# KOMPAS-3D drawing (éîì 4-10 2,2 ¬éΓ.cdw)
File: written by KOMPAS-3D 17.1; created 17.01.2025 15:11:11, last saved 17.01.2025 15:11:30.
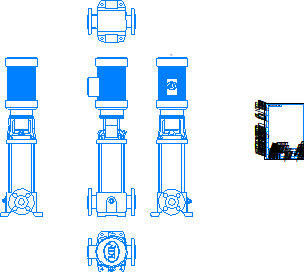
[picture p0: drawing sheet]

Sheet 1: A4, portrait

Title block, sheet 1: name: ВМН 4-10 2,2 кВт; designation: ВМН 4-10 2,2 кВт; sheets: 1; sheet format: A4; stored path: \\adlc.lan\data\АДЛ_ПКД\3D-модели\ADL production\Насосы ГРАНПАМП\Насосы ВМН\ВМН4\KOMPAS 2D\ВМН 4-10 2,2 кВт.cdw

Views: Вид 1, Спереди, Проекционный вид 2, Проекционный вид 3, Проекционный вид 4, Проекционный вид 5
Referenced files in \\adlc.lan\data\АДЛ_ПКД\3D-модели\ADL production\Насосы ГРАНПАМП\Насосы ВМН\ВМН4\KOMPAS 3D\: ВМН 4-10 2,2 кВт.m3d
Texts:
  Andrey
  АДЛ
Dimensions and other numbers on the sheet: 1:1; 1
